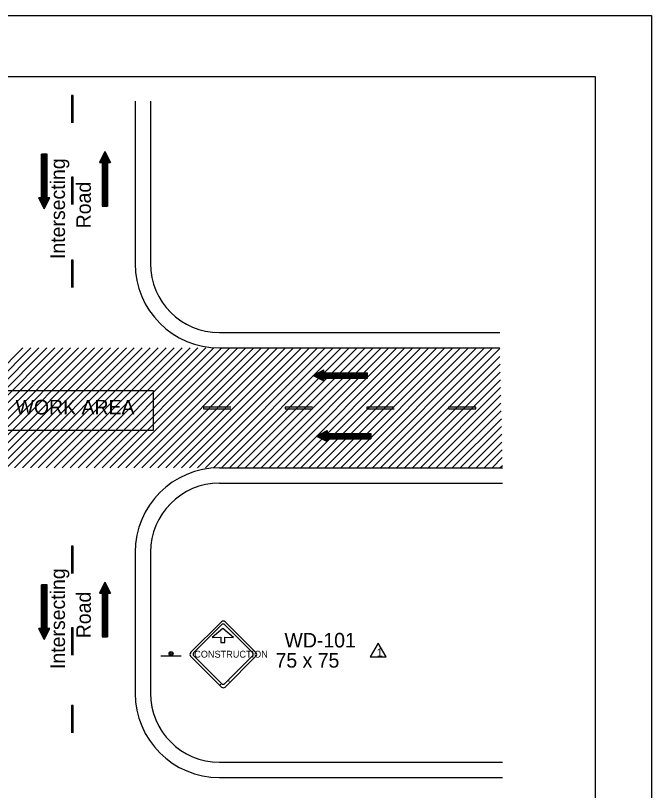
# Model space of a CAD drawing. Extents: x 2111 to 2327, y 208 to 487.
# Drawn here: x 2214.3 to 2327.3, y 349.6 to 487.2 of the extents above; entities that cross this region are included whole.
import ezdxf

# ---------------------------------------------------------------- set-up
doc = ezdxf.new("R2010")
doc.units = 0
for name, color, linetype in [('Level 1', 7, 'Continuous'), ('Level 10', 7, 'Continuous'), ('Level 2', 7, 'Continuous'), ('Level 44', 7, 'Continuous'), ('Level 60', 7, 'Continuous')]:
    doc.layers.add(name, color=color, linetype=linetype)

msp = doc.modelspace()

# ---------------------------------------------------------------- linework, layer by layer
at = {"layer": 'Level 1'}
msp.add_lwpolyline([(2278.72, 375.75), (2277.3, 373.28), (2280.14, 373.28)], close=True, dxfattribs=at)
at = {"layer": 'Level 10'}
for p, q in [((2235.56, 472.01), (2235.56, 443.16)), ((2238.29, 472.01), (2238.29, 443.16)), ((2218.94, 454.84), (2218.94, 462.58)), ((2219.91, 462.58), (2218.94, 462.58)), ((2218.94, 453.87), (2218.94, 462.58)), ((2219.06, 453.62), (2219.06, 462.58)), ((2219.18, 453.38), (2219.18, 462.58)), ((2219.3, 453.14), (2219.3, 462.58)), ((2219.42, 452.9), (2219.42, 462.58)), ((2219.54, 453.14), (2219.54, 462.58)), ((2219.66, 453.38), (2219.66, 462.58)), ((2219.78, 453.62), (2219.78, 462.58)), ((2219.91, 454.84), (2219.91, 462.58)), ((2219.91, 453.87), (2219.91, 462.58)), ((2230.19, 463.03), (2229.22, 461.09)), ((2229.95, 462.54), (2229.95, 453.35)), ((2230.07, 462.79), (2230.07, 453.35)), ((2230.19, 463.03), (2230.19, 453.35)), ((2230.19, 463.03), (2231.16, 461.09)), ((2230.31, 462.79), (2230.31, 453.35)), ((2230.43, 462.54), (2230.43, 453.35)), ((2229.22, 461.09), (2229.71, 461.09)), ((2229.35, 461.34), (2229.35, 461.09)), ((2229.47, 461.58), (2229.47, 461.09)), ((2229.59, 461.82), (2229.59, 461.09)), ((2229.71, 462.06), (2229.71, 453.35)), ((2229.71, 461.09), (2229.71, 453.35)), ((2229.83, 462.3), (2229.83, 453.35)), ((2230.56, 462.3), (2230.56, 453.35)), ((2230.68, 462.06), (2230.68, 453.35)), ((2230.68, 461.09), (2230.68, 453.35)), ((2230.68, 461.09), (2231.16, 461.09)), ((2230.8, 461.82), (2230.8, 461.09)), ((2230.92, 461.58), (2230.92, 461.09)), ((2231.04, 461.34), (2231.04, 461.09)), ((2219.42, 452.9), (2218.45, 454.84)), ((2218.94, 454.84), (2218.45, 454.84)), ((2218.58, 454.59), (2218.58, 454.84)), ((2218.7, 454.35), (2218.7, 454.84)), ((2218.82, 454.11), (2218.82, 454.84)), ((2219.42, 452.9), (2220.39, 454.84)), ((2220.39, 454.84), (2219.91, 454.84)), ((2220.03, 454.11), (2220.03, 454.84)), ((2220.15, 454.35), (2220.15, 454.84)), ((2220.27, 454.59), (2220.27, 454.84)), ((2229.71, 453.35), (2230.68, 453.35)), ((2250.56, 430.89), (2300.35, 430.89)), ((2194.32, 406.87), (2215.62, 428.16)), ((2195.74, 406.87), (2217.03, 428.16)), ((2197.15, 406.87), (2218.45, 428.16)), ((2198.56, 406.87), (2219.86, 428.16)), ((2199.98, 406.87), (2221.27, 428.16)), ((2201.39, 406.87), (2222.69, 428.16)), ((2202.81, 406.87), (2224.1, 428.16)), ((2204.22, 406.87), (2225.52, 428.16)), ((2205.64, 406.87), (2226.93, 428.16)), ((2207.05, 406.87), (2228.35, 428.16)), ((2208.46, 406.87), (2229.76, 428.16)), ((2209.88, 406.87), (2231.17, 428.16)), ((2211.29, 406.87), (2232.59, 428.16)), ((2212.71, 406.87), (2234, 428.16)), ((2214.12, 406.87), (2235.42, 428.16)), ((2215.53, 406.87), (2236.83, 428.16)), ((2216.95, 406.87), (2238.24, 428.16)), ((2218.36, 406.87), (2239.66, 428.16)), ((2219.78, 406.87), (2241.07, 428.16)), ((2221.19, 406.87), (2242.49, 428.16)), ((2222.61, 406.87), (2243.9, 428.16)), ((2224.02, 406.87), (2245.32, 428.16)), ((2225.43, 406.87), (2246.73, 428.16)), ((2226.85, 406.87), (2248.14, 428.16)), ((2228.26, 406.87), (2249.56, 428.16)), ((2229.68, 406.87), (2250.97, 428.16)), ((2231.09, 406.87), (2252.39, 428.16)), ((2232.51, 406.87), (2253.8, 428.16)), ((2233.92, 406.87), (2255.22, 428.16)), ((2235.34, 406.87), (2256.63, 428.16)), ((2236.75, 406.87), (2258.04, 428.16)), ((2238.16, 406.87), (2259.46, 428.16)), ((2239.58, 406.87), (2260.87, 428.16)), ((2240.99, 406.87), (2262.29, 428.16)), ((2242.41, 406.87), (2263.7, 428.16)), ((2243.82, 406.87), (2265.12, 428.16)), ((2245.24, 406.87), (2266.53, 428.16)), ((2246.65, 406.87), (2267.94, 428.16)), ((2248.06, 406.87), (2269.36, 428.16)), ((2249.48, 406.87), (2270.77, 428.16)), ((2250.56, 428.16), (2300.35, 428.16)), ((2250.89, 406.87), (2272.19, 428.16)), ((2252.31, 406.87), (2273.6, 428.16)), ((2253.72, 406.87), (2275.01, 428.16)), ((2255.14, 406.87), (2276.43, 428.16)), ((2256.55, 406.87), (2277.84, 428.16)), ((2257.96, 406.87), (2279.26, 428.16)), ((2259.38, 406.87), (2280.67, 428.16)), ((2260.79, 406.87), (2282.09, 428.16)), ((2262.21, 406.87), (2283.5, 428.16)), ((2263.62, 406.87), (2284.91, 428.16)), ((2265.03, 406.87), (2286.33, 428.16)), ((2266.45, 406.87), (2287.74, 428.16)), ((2267.86, 406.87), (2289.16, 428.16)), ((2269.28, 406.87), (2290.57, 428.16)), ((2270.69, 406.87), (2291.99, 428.16)), ((2272.11, 406.87), (2293.4, 428.16)), ((2273.52, 406.87), (2294.81, 428.16)), ((2274.93, 406.87), (2296.23, 428.16)), ((2276.35, 406.87), (2297.64, 428.16)), ((2277.76, 406.87), (2299.06, 428.16)), ((2279.18, 406.87), (2300.35, 428.04)), ((2280.59, 406.87), (2300.38, 426.66)), ((2267.19, 423.29), (2269.12, 424.25)), ((2268.64, 424.01), (2269.12, 424.01)), ((2268.88, 424.13), (2269.12, 424.13)), ((2269.12, 423.77), (2269.12, 424.25)), ((2282.01, 406.87), (2300.41, 425.28)), ((2267.19, 423.29), (2276.87, 423.29)), ((2267.19, 423.29), (2269.12, 422.32)), ((2267.43, 423.41), (2276.87, 423.41)), ((2267.43, 423.17), (2276.87, 423.17)), ((2267.67, 423.53), (2276.87, 423.53)), ((2267.67, 423.05), (2276.87, 423.05)), ((2267.92, 423.65), (2276.87, 423.65)), ((2267.92, 422.92), (2276.87, 422.92)), ((2268.16, 423.77), (2276.87, 423.77)), ((2268.16, 422.8), (2276.87, 422.8)), ((2268.4, 423.89), (2269.12, 423.89)), ((2268.4, 422.68), (2269.12, 422.68)), ((2268.64, 422.56), (2269.12, 422.56)), ((2269.12, 423.77), (2276.87, 423.77)), ((2269.12, 422.8), (2276.87, 422.8)), ((2269.12, 422.32), (2269.12, 422.8)), ((2276.87, 422.8), (2276.87, 423.77)), ((2283.42, 406.87), (2300.45, 423.89)), ((2268.88, 422.44), (2269.12, 422.44)), ((2284.84, 406.87), (2300.48, 422.51)), ((2286.25, 406.87), (2300.51, 421.13)), ((2287.66, 406.87), (2300.54, 419.75)), ((2289.08, 406.87), (2300.57, 418.37)), ((2290.49, 406.87), (2300.61, 416.98)), ((2291.91, 406.87), (2300.64, 415.6)), ((2267.77, 412.52), (2269.7, 413.49)), ((2268.74, 413), (2277.45, 413)), ((2268.98, 413.12), (2269.7, 413.12)), ((2269.22, 413.24), (2269.7, 413.24)), ((2269.46, 413.36), (2269.7, 413.36)), ((2269.7, 413.49), (2269.7, 413)), ((2269.7, 413), (2277.45, 413)), ((2277.45, 413), (2277.45, 412.03)), ((2293.32, 406.87), (2300.67, 414.22)), ((2267.77, 412.52), (2277.45, 412.52)), ((2267.77, 412.52), (2269.7, 411.55)), ((2268.01, 412.64), (2277.45, 412.64)), ((2268.01, 412.4), (2277.45, 412.4)), ((2268.25, 412.76), (2277.45, 412.76)), ((2268.25, 412.28), (2277.45, 412.28)), ((2268.49, 412.88), (2277.45, 412.88)), ((2268.49, 412.15), (2277.45, 412.15)), ((2268.74, 412.03), (2277.45, 412.03)), ((2268.98, 411.91), (2269.7, 411.91)), ((2269.22, 411.79), (2269.7, 411.79)), ((2269.46, 411.67), (2269.7, 411.67)), ((2269.7, 412.03), (2277.45, 412.03)), ((2269.7, 412.03), (2269.7, 411.55)), ((2294.74, 406.87), (2300.7, 412.84)), ((2296.15, 406.87), (2300.73, 411.45)), ((2297.56, 406.87), (2300.76, 410.07)), ((2298.98, 406.87), (2300.8, 408.69)), ((2250.56, 406.87), (2300.84, 406.87)), ((2300.39, 406.87), (2300.83, 407.31)), ((2250.56, 404.14), (2300.84, 404.14)), ((2235.56, 391.87), (2235.56, 366.87)), ((2238.29, 391.87), (2238.29, 366.87)), ((2218.94, 378.35), (2218.94, 386.09)), ((2219.91, 386.09), (2218.94, 386.09)), ((2218.94, 377.38), (2218.94, 386.09)), ((2219.06, 377.14), (2219.06, 386.09)), ((2219.18, 376.9), (2219.18, 386.09)), ((2219.3, 376.66), (2219.3, 386.09)), ((2219.42, 376.41), (2219.42, 386.09)), ((2219.54, 376.66), (2219.54, 386.09)), ((2219.66, 376.9), (2219.66, 386.09)), ((2219.78, 377.14), (2219.78, 386.09)), ((2219.91, 378.35), (2219.91, 386.09)), ((2219.91, 377.38), (2219.91, 386.09)), ((2230.19, 386.54), (2229.22, 384.61)), ((2229.71, 385.57), (2229.71, 376.87)), ((2229.83, 385.82), (2229.83, 376.87)), ((2229.95, 386.06), (2229.95, 376.87)), ((2230.07, 386.3), (2230.07, 376.87)), ((2230.19, 386.54), (2230.19, 376.87)), ((2230.19, 386.54), (2231.16, 384.61)), ((2230.31, 386.3), (2230.31, 376.87)), ((2230.43, 386.06), (2230.43, 376.87)), ((2230.56, 385.82), (2230.56, 376.87)), ((2230.68, 385.57), (2230.68, 376.87)), ((2229.22, 384.61), (2229.71, 384.61)), ((2229.35, 384.85), (2229.35, 384.61)), ((2229.47, 385.09), (2229.47, 384.61)), ((2229.59, 385.33), (2229.59, 384.61)), ((2229.71, 384.61), (2229.71, 376.87)), ((2230.68, 384.61), (2230.68, 376.87)), ((2230.68, 384.61), (2231.16, 384.61)), ((2230.8, 385.33), (2230.8, 384.61)), ((2230.92, 385.09), (2230.92, 384.61)), ((2231.04, 384.85), (2231.04, 384.61)), ((2219.42, 376.41), (2218.45, 378.35)), ((2218.94, 378.35), (2218.45, 378.35)), ((2218.58, 378.11), (2218.58, 378.35)), ((2218.7, 377.87), (2218.7, 378.35)), ((2218.82, 377.62), (2218.82, 378.35)), ((2219.42, 376.41), (2220.39, 378.35)), ((2220.39, 378.35), (2219.91, 378.35)), ((2220.03, 377.62), (2220.03, 378.35)), ((2220.15, 377.87), (2220.15, 378.35)), ((2220.27, 378.11), (2220.27, 378.35)), ((2229.71, 376.87), (2230.68, 376.87)), ((2250.56, 354.6), (2300.84, 354.6)), ((2250.56, 351.87), (2300.84, 351.87))]:
    msp.add_line(p, q, dxfattribs=at)
msp.add_lwpolyline([(2210.93, 420.62), (2238.78, 420.62), (2238.78, 413.5), (2210.93, 413.5)], close=True, dxfattribs=at)
for centre, radius, start, end in [((2250.56, 443.16), 15, 180, 270), ((2250.56, 443.16), 12.27, 180, 270), ((2250.56, 391.87), 15, 90, 180), ((2250.56, 391.87), 12.27, 90, 180), ((2250.56, 366.87), 15, 180, 270), ((2250.56, 366.87), 12.27, 180, 270)]:
    msp.add_arc(centre, radius, start, end, dxfattribs=at)
at = {"layer": 'Level 2'}
for p, q in [((2224.26, 472.99), (2224.26, 468.15)), ((2224.55, 472.99), (2224.26, 472.99)), ((2224.55, 468.15), (2224.55, 472.99)), ((2224.26, 458.47), (2224.26, 453.63)), ((2224.55, 458.47), (2224.26, 458.47)), ((2224.55, 453.63), (2224.55, 458.47)), ((2224.26, 443.73), (2224.26, 438.89)), ((2224.55, 443.73), (2224.26, 443.73)), ((2224.55, 438.89), (2224.55, 443.73)), ((2252.57, 417.62), (2247.73, 417.62)), ((2247.73, 417.62), (2247.73, 417.33)), ((2247.73, 417.33), (2252.57, 417.33)), ((2267.08, 417.62), (2262.24, 417.62)), ((2262.24, 417.62), (2262.24, 417.33)), ((2262.24, 417.33), (2267.08, 417.33)), ((2281.59, 417.62), (2276.76, 417.62)), ((2276.76, 417.62), (2276.76, 417.33)), ((2276.76, 417.33), (2281.59, 417.33)), ((2296.11, 417.62), (2291.27, 417.62)), ((2291.27, 417.62), (2291.27, 417.33)), ((2291.27, 417.33), (2296.11, 417.33)), ((2296.11, 417.33), (2296.11, 417.62)), ((2224.26, 392.94), (2224.26, 388.1)), ((2224.55, 392.94), (2224.26, 392.94)), ((2224.55, 388.1), (2224.55, 392.94)), ((2224.26, 378.43), (2224.26, 373.59)), ((2224.55, 378.43), (2224.26, 378.43)), ((2224.55, 373.59), (2224.55, 378.43)), ((2252.25, 369.01), (2252.15, 368.91)), ((2250.8, 368.44), (2250.69, 368.34)), ((2224.26, 364.68), (2224.26, 359.84)), ((2224.55, 364.68), (2224.26, 364.68)), ((2224.55, 359.84), (2224.55, 364.68))]:
    msp.add_line(p, q, dxfattribs=at)
at = {"layer": 'Level 44'}
for p, q in [((2250.91, 379.54), (2245.43, 374.07)), ((2245.98, 374.06), (2250.91, 378.99)), ((2251.5, 378.99), (2256.42, 374.06)), ((2257.03, 374.07), (2251.56, 379.54)), ((2251.16, 378.34), (2249.27, 376.75)), ((2253.04, 376.75), (2251.16, 378.34)), ((2249.27, 376.75), (2250.78, 376.83)), ((2250.78, 376.83), (2250.78, 375.83)), ((2250.78, 375.83), (2251.53, 375.83)), ((2251.53, 375.83), (2251.53, 376.83)), ((2251.53, 376.83), (2253.04, 376.75)), ((2240.12, 373.48), (2243.75, 373.48)), ((2245.43, 373.42), (2250.91, 367.94)), ((2245.44, 373.42), (2245.43, 373.42)), ((2250.91, 368.55), (2245.98, 373.48)), ((2256.42, 373.48), (2251.5, 368.55)), ((2251.56, 367.94), (2257.03, 373.42))]:
    msp.add_line(p, q, dxfattribs=at)
for radius in [0.363, 0.181]:
    msp.add_circle((2241.95, 373.88), radius, dxfattribs=at)
for centre, radius, start, end in [((2251.24, 379.21), 0.458, 45, 135), ((2251.2, 378.7), 0.412, 45, 135), ((2245.76, 373.74), 0.458, 135, 225), ((2246.28, 373.77), 0.412, 135, 225), ((2256.13, 373.77), 0.412, 315, 45), ((2256.71, 373.74), 0.458, 315, 45), ((2251.2, 368.84), 0.412, 225, 315), ((2251.24, 368.27), 0.458, 225, 315)]:
    msp.add_arc(centre, radius, start, end, dxfattribs=at)
at = {"layer": 'Level 60'}
for points in [[(2111.32, 487.21), (2327.32, 487.21), (2327.32, 208.21), (2111.32, 208.21)], [(2130.44, 476.4), (2317.32, 476.4), (2317.32, 219.02), (2130.44, 219.02)]]:
    msp.add_lwpolyline(points, close=True, dxfattribs=at)

# ---------------------------------------------------------------- texts
at = {"layer": 'Level 1'}
msp.add_text('1', height=1.45, rotation=360, dxfattribs=at).set_placement((2278.49, 373.34))
at = {"layer": 'Level 10'}
for s, p in [('Intersecting', (2223.1, 443.96)), ('Road', (2227.69, 449.41)), ('Intersecting', (2223.1, 371.15)), ('Road', (2227.69, 376.61))]:
    msp.add_text(s, height=2.585, rotation=90, dxfattribs=at).set_placement(p)
for s, p in [('WORK AREA', (2214.32, 416.36)), ('WD-101', (2262.1, 374.97)), ('75 x 75', (2260.51, 371.39))]:
    msp.add_text(s, height=2.585, dxfattribs=at).set_placement(p)
at = {"layer": 'Level 44'}
msp.add_text('CONSTRUCTION', height=1.2148, rotation=360, dxfattribs=at).set_placement((2246.06, 373.17))

doc.saveas('drawing.dxf')
